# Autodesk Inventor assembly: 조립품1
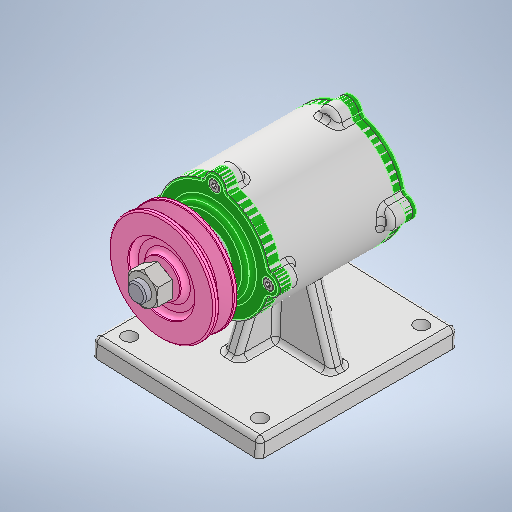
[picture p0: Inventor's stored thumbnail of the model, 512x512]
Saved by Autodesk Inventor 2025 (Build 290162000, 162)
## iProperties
Created: 2025-08
Part Number: 조립품1
Document SubType Name: Assembly
Designer: infra04
Author: infra04
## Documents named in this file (10)
- C:\Users\infra04\Desktop\750806V1004\조립품1.iam
- C:\Users\infra04\Desktop\750806V1004\부품도면.ipt
- C:\Users\infra04\Desktop\750806V1004\베어링 6204\베어링 6204.ipt
- C:\Users\infra04\Desktop\750806V1004\볼트 M4 x 12\볼트 M4 x 12.ipt
- C:\Users\infra04\Desktop\750806V1004\앞커버\앞커버.ipt
- C:\Users\infra04\Desktop\750806V1004\축\축.ipt
- C:\Users\infra04\Desktop\750806V1004\키 4 x 4\키 4 x 4.ipt
- C:\Users\infra04\Desktop\750806V1004\V-벨트풀리\V-벨트풀리.ipt
- C:\Users\infra04\Desktop\750806V1004\너트 M12 x 1.25\너트 M12 x 1.25.ipt
- C:\Users\infra04\Desktop\750806V1004\뒤커버\뒤커버.ipt
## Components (1 placed, 1 different names)
1. V-벨트풀리:1
